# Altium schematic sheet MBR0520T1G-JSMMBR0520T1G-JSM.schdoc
size 127 x 101 mm
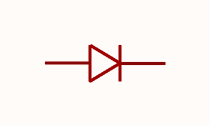
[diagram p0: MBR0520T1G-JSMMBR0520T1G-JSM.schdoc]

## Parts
D?  mbr0520t1g-jsm  [SOD-123_L2.7-W1.6-LS3.7-FD]  (value not drawn)

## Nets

Not connected (* = marked no-connect by the designer): D? 1(A) 2(K)

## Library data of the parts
D? = mbr0520t1g-jsm: 二极管配置:1个独立式;正向压降(Vf):300mV@0.1A;直流反向耐压(Vr):20V;整流电流:500mA;; Manufacturer: JSMSEMI(杰盛微); AddInBom: yes; ModelId: 5054d9b7be8b429dad093a54b517b4dd; ModelTransform: 145.669,61.024,0,0,0,0,0,0,0; Diode Configuration: 1个独立式; Voltage - DC Reverse(Vr): 20V; Current - Rectified: 500mA; Reverse Leakage Current (Ir): 75uA@10V; Operating Junction Temperature Range: -65℃~+100℃; Non-Repetitive Peak Forward Surge Current: 5.5A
